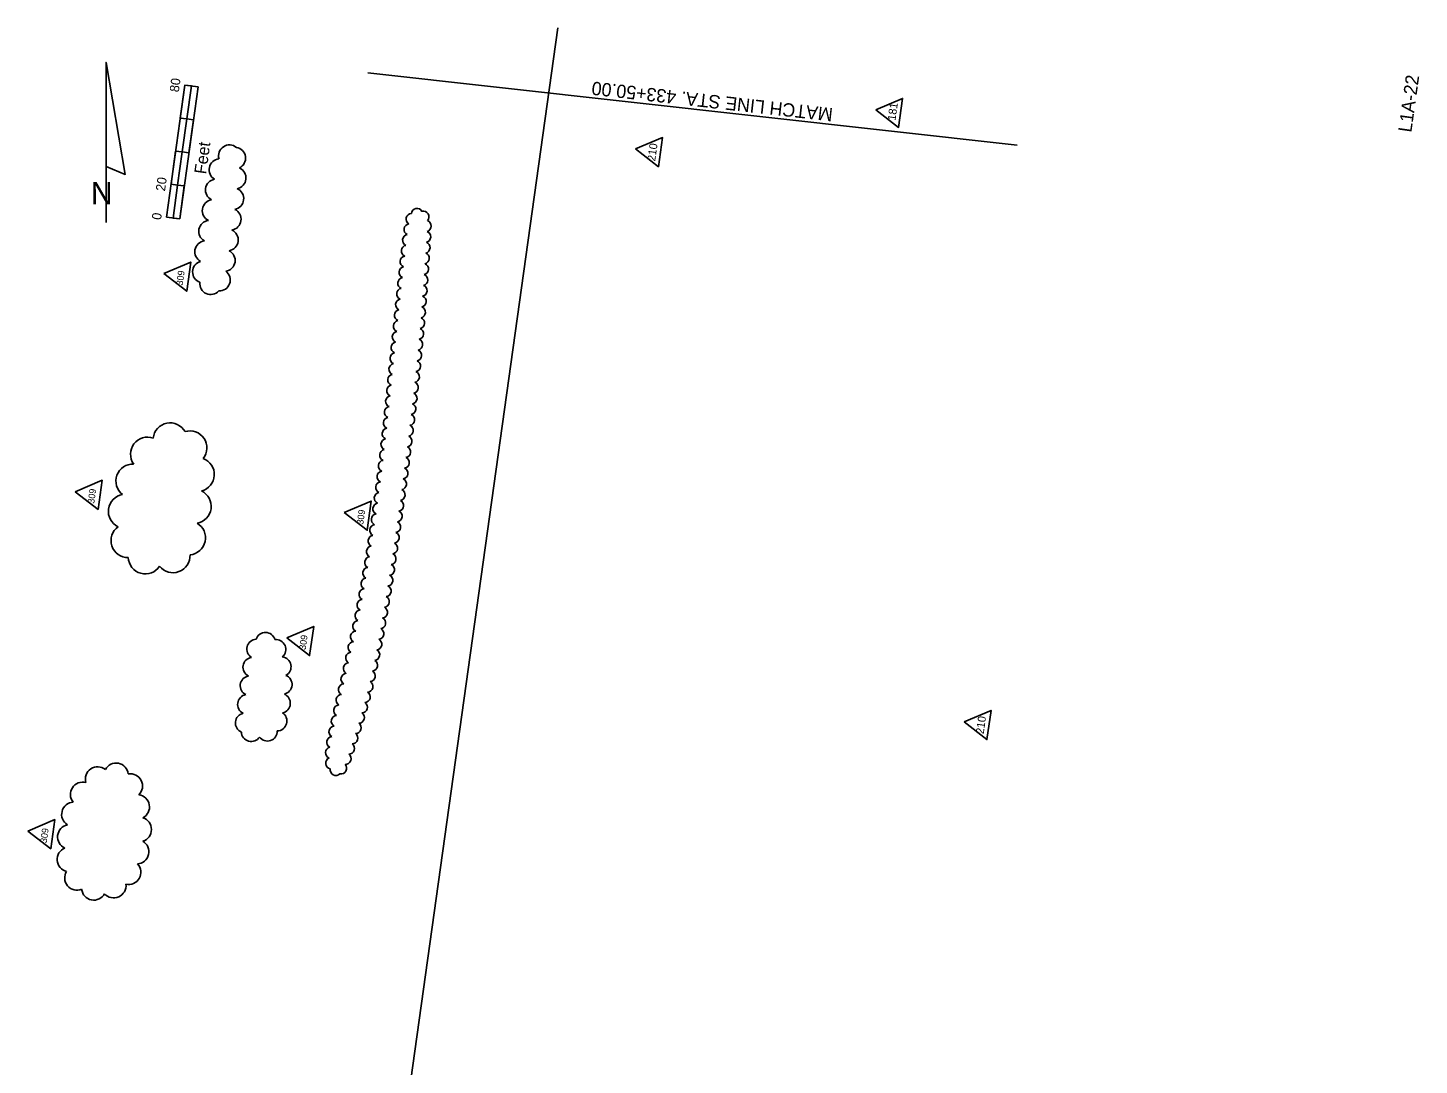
# Model space of a CAD drawing. Extents: x 930268 to 931132, y 618295 to 619577.
# Drawn here: x 930298 to 931132, y 618955 to 619577 of the extents above; entities that cross this region are included whole.
import ezdxf

# ---------------------------------------------------------------- set-up
doc = ezdxf.new("R2010")
doc.units = 0
for name, color, linetype in [('ActivePointCell_dp', 7, 'Continuous'), ('Cloud_dp', 7, 'Continuous'), ('MatchLines_dp', 7, 'Continuous'), ('NorthArw_dp', 7, 'Continuous'), ('Scale_dp', 7, 'Continuous'), ('TextShtNo', 7, 'Continuous')]:
    doc.layers.add(name, color=color, linetype=linetype)

msp = doc.modelspace()

# ---------------------------------------------------------------- linework, layer by layer
at = {"layer": 'ActivePointCell_dp'}
msp.add_line((930462.95, 618484.75), (930615.71, 619576.99), dxfattribs=at)
at = {"layer": 'Cloud_dp'}
for points in [[(930806.31, 619527.85), (930820.02, 619517.23), (930822.47, 619534.71)], [(930662.34, 619504.35), (930676.04, 619493.73), (930678.49, 619511.21)], [(930379.36, 619429.69), (930393.07, 619419.07), (930395.51, 619436.55)], [(930326.25, 619298.86), (930339.96, 619288.24), (930342.4, 619305.72)], [(930487.61, 619286.33), (930501.32, 619275.71), (930503.76, 619293.19)], [(930453.09, 619211.2), (930466.8, 619200.58), (930469.24, 619218.06)], [(930859.35, 619160.86), (930873.05, 619150.24), (930875.5, 619167.72)], [(930297.78, 619095.34), (930311.49, 619084.72), (930313.94, 619102.2)]]:
    msp.add_lwpolyline(points, close=True, dxfattribs=at)
for centre, radius, start, end in [((930418.74, 619500.23), 6.55, 51.03585, 196.03585), ((930421.82, 619498.86), 6.55, 295.85716, 80.85716), ((930413.06, 619491.9), 6.55, 95.41506, 240.41506), ((930422.08, 619486.95), 6.55, 281.58955, 66.58955), ((930410.85, 619479.72), 6.55, 98.97996, 243.97996), ((930420.71, 619474.55), 6.55, 280.79342, 65.79342), ((930408.98, 619467.36), 6.55, 98.77594, 243.77594), ((930419.13, 619462.18), 6.55, 279.66877, 64.66877), ((930528.06, 619462.32), 3.4, 94.2635, 239.2635), ((930531.18, 619465.33), 3.4, 28.62723, 173.62723), ((930534.93, 619463.65), 3.4, 317.95106, 102.95106), ((930406.83, 619454.96), 6.55, 96.59395, 241.59395), ((930417.41, 619449.81), 6.55, 279.53834, 64.53834), ((930526.82, 619456.04), 3.4, 98.56091, 243.56091), ((930536.31, 619458.17), 3.4, 285.40798, 70.40798), ((930404.47, 619442.69), 6.55, 96.60881, 241.60881), ((930525.19, 619443.22), 3.4, 101.14559, 246.14559), ((930525.94, 619449.65), 3.4, 100.60541, 245.60541), ((930535.62, 619445.25), 3.4, 283.84678, 68.84678), ((930536.01, 619451.72), 3.4, 284.24885, 69.24885), ((930415.59, 619437.47), 6.55, 278.67941, 63.67941), ((930524.48, 619436.78), 3.4, 101.31323, 246.31323), ((930535.19, 619438.79), 3.4, 283.62171, 68.62171), ((930403.15, 619430.62), 6.55, 105.91825, 250.91825), ((930412.62, 619425.77), 6.56, 267.76128, 52.76128), ((930523.79, 619430.34), 3.4, 101.40488, 246.40488), ((930534.75, 619432.32), 3.4, 283.47261, 68.47261), ((930407.5, 619423.61), 6.55, 172.86138, 317.86138), ((930523.1, 619423.89), 3.4, 101.46493, 246.46493), ((930533.81, 619419.39), 3.4, 283.28136, 68.28136), ((930534.28, 619425.86), 3.4, 283.36446, 68.36446), ((930521.75, 619411), 3.4, 101.54129, 246.54129), ((930522.42, 619417.44), 3.4, 101.50819, 246.50819), ((930533.33, 619412.93), 3.4, 283.21492, 68.21492), ((930521.08, 619404.55), 3.4, 101.56767, 246.56767), ((930532.84, 619406.46), 3.4, 283.04867, 68.04867), ((930520.41, 619398.1), 3.4, 101.58934, 246.58934), ((930531.76, 619393.55), 3.4, 282.42953, 67.42953), ((930532.32, 619400.01), 3.4, 282.72551, 67.72551), ((930519.08, 619385.2), 3.4, 101.62314, 246.62314), ((930519.74, 619391.65), 3.4, 101.60755, 246.60755), ((930531.17, 619387.1), 3.4, 282.15902, 67.15902), ((930518.42, 619378.75), 3.4, 101.63667, 246.63667), ((930530.56, 619380.65), 3.4, 281.91054, 66.91054), ((930517.75, 619372.3), 3.4, 101.64857, 246.64857), ((930529.91, 619374.21), 3.4, 281.68127, 66.68127), ((930517.09, 619365.86), 3.4, 101.65914, 246.65914), ((930528.55, 619361.32), 3.4, 281.27135, 66.27135), ((930529.24, 619367.76), 3.4, 281.46886, 66.46886), ((930515.77, 619352.96), 3.4, 101.64316, 246.64316), ((930516.43, 619359.41), 3.4, 101.66861, 246.66861), ((930527.84, 619354.88), 3.4, 281.08709, 66.08709), ((930515.1, 619346.5), 3.4, 101.48523, 246.48523), ((930527.1, 619348.44), 3.4, 280.91465, 65.91465), ((930383.16, 619329.91), 10.21, 29.0425, 174.0425), ((930514.41, 619340.05), 3.4, 101.30816, 246.30816), ((930525.58, 619335.57), 3.4, 280.60059, 65.60059), ((930526.35, 619342), 3.4, 280.75283, 65.75283), ((930369.59, 619321.35), 10.21, 70.43086, 215.43086), ((930395, 619325.08), 10.21, 321.57868, 106.57868), ((930512.97, 619327.16), 3.4, 100.93203, 245.93203), ((930513.7, 619333.61), 3.4, 101.12392, 246.12392), ((930524.8, 619329.13), 3.4, 280.45702, 65.45702), ((930512.22, 619320.72), 3.4, 100.73193, 245.73193), ((930523.99, 619322.7), 3.4, 280.32133, 65.32133), ((930360.79, 619305.23), 10.2, 87.35809, 232.35809), ((930399.41, 619309.18), 10.21, 284.44255, 69.44255), ((930511.44, 619314.28), 3.4, 100.52304, 245.52304), ((930523.18, 619316.27), 3.4, 280.19283, 65.19283), ((930509.82, 619301.41), 3.4, 100.0762, 245.0762), ((930510.64, 619307.84), 3.4, 100.30471, 245.30471), ((930521.5, 619303.42), 3.4, 279.95501, 64.95501), ((930522.35, 619309.85), 3.4, 280.0709, 65.0709), ((930356.3, 619287.09), 10.21, 99.79905, 244.79905), ((930397.57, 619290.08), 10.21, 279.53833, 64.53833), ((930508.97, 619294.97), 3.4, 99.83672, 244.83672), ((930520.64, 619297), 3.4, 279.84467, 64.84467), ((930508.09, 619288.55), 3.4, 99.58538, 244.58538), ((930519.77, 619290.57), 3.4, 279.73945, 64.73945), ((930394.16, 619271.16), 10.21, 275.04032, 60.04032), ((930507.18, 619282.12), 3.4, 99.32117, 244.32117), ((930518, 619277.73), 3.4, 279.53642, 64.53642), ((930518.89, 619284.15), 3.4, 279.63898, 64.63898), ((930357.92, 619269.57), 10.21, 125.77647, 270.77647), ((930505.27, 619269.29), 3.4, 98.74954, 243.74954), ((930506.24, 619275.7), 3.4, 99.04297, 244.04297), ((930517.1, 619271.31), 3.4, 279.38533, 64.38533), ((930504.26, 619262.88), 3.4, 98.43945, 243.43945), ((930516.17, 619264.9), 3.4, 279.21333, 64.21333), ((930368.26, 619259.74), 10.21, 182.09907, 327.09907), ((930384.87, 619260.47), 10.2, 217.94624, 2.94624), ((930503.22, 619256.47), 3.4, 98.11108, 243.11108), ((930514.26, 619252.08), 3.4, 278.82585, 63.82585), ((930515.23, 619258.49), 3.4, 279.0275, 64.0275), ((930501.03, 619243.68), 3.4, 97.39196, 242.39196), ((930502.15, 619250.07), 3.4, 97.76262, 242.76262), ((930513.27, 619245.68), 3.4, 278.60604, 63.60604), ((930499.87, 619237.29), 3.4, 96.9967, 241.9967), ((930512.26, 619239.28), 3.4, 278.36516, 63.36516), ((930498.66, 619230.91), 3.4, 96.57405, 241.57405), ((930511.21, 619232.89), 3.4, 278.09964, 63.09964), ((930496.1, 619218.19), 3.4, 95.63307, 240.63307), ((930497.4, 619224.55), 3.4, 96.12077, 241.12077), ((930509.03, 619220.12), 3.4, 277.47547, 62.47547), ((930510.14, 619226.5), 3.4, 277.80499, 62.80499), ((930440.34, 619208.53), 5.91, 16.48006, 161.48006), ((930494.73, 619211.84), 3.4, 95.10647, 240.10647), ((930507.88, 619213.74), 3.4, 277.10366, 62.10366), ((930435.03, 619204.49), 5.92, 92.83477, 237.83477), ((930446.58, 619204.31), 5.92, 310.5213, 95.5213), ((930493.31, 619205.5), 3.4, 94.65292, 239.65292), ((930506.69, 619207.38), 3.4, 276.67972, 61.67972), ((930432.75, 619193.62), 5.92, 98.47078, 243.47078), ((930449.75, 619193.93), 5.92, 298.43365, 83.43365), ((930490.42, 619192.86), 3.4, 94.61213, 239.61213), ((930491.87, 619199.18), 3.4, 94.61213, 239.61213), ((930504.14, 619194.68), 3.4, 275.61665, 60.61665), ((930505.45, 619201.02), 3.4, 276.19028, 61.19028), ((930431.08, 619182.49), 5.92, 99.53523, 244.53523), ((930450.33, 619183.25), 5.92, 282.70157, 67.70157), ((930488.98, 619186.54), 3.4, 94.61213, 239.61213), ((930502.77, 619188.36), 3.4, 274.93174, 59.93174), ((930487.53, 619180.22), 3.4, 94.61213, 239.61213), ((930501.32, 619182.05), 3.4, 274.09455, 59.09455), ((930429.52, 619171.31), 5.92, 99.53834, 244.53834), ((930449.31, 619172.03), 5.92, 281.93636, 66.93636), ((930486.09, 619173.9), 3.4, 94.61213, 239.61213), ((930498.08, 619169.55), 3.4, 271.65306, 56.65306), ((930499.76, 619175.78), 3.4, 273.0394, 58.0394), ((930428.18, 619160.17), 5.92, 101.74986, 246.74986), ((930447.27, 619161.3), 5.92, 271.49546, 56.49546), ((930483.19, 619161.26), 3.4, 94.61213, 239.61213), ((930484.64, 619167.58), 3.4, 94.61213, 239.61213), ((930496.24, 619163.35), 3.4, 270.35906, 55.35906), ((930431.76, 619154.95), 5.92, 182.16202, 327.16202), ((930441.5, 619155.25), 5.92, 216.33339, 1.33339), ((930481.75, 619154.94), 3.4, 94.61213, 239.61213), ((930494.32, 619157.17), 3.4, 270.04193, 55.04193), ((930480.45, 619148.64), 3.4, 97.08753, 242.08753), ((930490.33, 619144.85), 3.4, 269.01972, 54.01972), ((930492.35, 619151), 3.4, 269.64748, 54.64748), ((930479.71, 619142.34), 3.4, 104.56702, 249.56702), ((930479.88, 619136.04), 3.4, 113.54659, 258.54659), ((930488.22, 619138.74), 3.4, 267.75881, 52.75881), ((930339.66, 619126.5), 7.35, 51.12543, 196.12543), ((930350.75, 619128.75), 7.34, 6.79611, 151.79611), ((930359.22, 619122.36), 7.35, 314.26269, 99.26269), ((930482.55, 619132.1), 3.4, 169.56287, 314.56287), ((930485.61, 619133.01), 3.4, 258.38989, 43.38989), ((930330.65, 619117.37), 7.35, 74.57631, 219.57631), ((930363.41, 619109.81), 7.35, 297.6514, 82.6514), ((930325.41, 619105.35), 7.35, 93.34908, 238.34908), ((930322.97, 619091.88), 7.35, 101.10119, 246.10119), ((930364.6, 619096.29), 7.35, 287.35003, 72.35003), ((930363.03, 619082.96), 7.35, 274.23007, 59.23007), ((930322.71, 619078.33), 7.35, 111.73507, 256.73507), ((930327.23, 619067.23), 7.35, 147.55245, 292.55245), ((930358.19, 619070.62), 7.35, 257.90374, 42.90374), ((930349.34, 619062.64), 7.35, 221.23386, 6.23386), ((930337.35, 619061.29), 7.35, 186.59891, 331.59891)]:
    msp.add_arc(centre, radius, start, end, dxfattribs=at)
at = {"layer": 'MatchLines_dp'}
msp.add_line((930891.08, 619506.7), (930501.76, 619550.07), dxfattribs=at)
at = {"layer": 'NorthArw_dp'}
msp.add_line((930344.73, 619460.27), (930344.73, 619556.27), dxfattribs=at)
msp.add_lwpolyline([(930344.73, 619493.87), (930344.73, 619556.27), (930356.25, 619489.07)], close=True, dxfattribs=at)
at = {"layer": 'Scale_dp'}
for p, q in [((930391.96, 619542.71), (930380.93, 619463.47)), ((930388.86, 619462.37), (930399.88, 619541.6)), ((930399.88, 619541.6), (930391.96, 619542.71)), ((930380.93, 619463.47), (930388.86, 619462.37))]:
    msp.add_line(p, q, dxfattribs=at)
for points in [[(930393.16, 619522.35), (930389.2, 619522.9), (930391.96, 619542.71), (930395.92, 619542.16)], [(930394.37, 619501.99), (930390.41, 619502.54), (930393.16, 619522.35), (930397.12, 619521.8)], [(930387.65, 619482.73), (930383.69, 619483.28), (930386.44, 619503.09), (930390.41, 619502.54)], [(930388.86, 619462.37), (930384.89, 619462.92), (930387.65, 619482.73), (930391.61, 619482.18)]]:
    msp.add_lwpolyline(points, close=True, dxfattribs=at)

# ---------------------------------------------------------------- texts
at = {"layer": 'Cloud_dp'}
for s, height, p in [('181', 4.799, (930818.14, 619521.17)), ('210', 4.799, (930674.04, 619496.8)), ('309', 4, (930390.68, 619422.31)), ('309', 4, (930337.57, 619291.48)), ('309', 4, (930498.93, 619278.96)), ('309', 4, (930464.41, 619203.82)), ('210', 4.799, (930871.05, 619153.31)), ('309', 4, (930309.11, 619087.96))]:
    msp.add_text(s, height=height, rotation=82.03834, dxfattribs=at).set_placement(p)
at = {"layer": 'MatchLines_dp'}
msp.add_text('MATCH LINE STA. 433+50.00', height=8, rotation=173.6425, dxfattribs=at).set_placement((930780.96, 619528.77))
at = {"layer": 'NorthArw_dp'}
msp.add_text('N', height=13.43, dxfattribs=at).set_placement((930335.61, 619471.14))
at = {"layer": 'Scale_dp'}
for s, height, p in [('80', 5.6, (930388.3, 619538.19)), ('Feet', 7.2, (930404.67, 619488.98)), ('20', 5.6, (930380.03, 619478.78)), ('0', 5.6, (930377.64, 619461.58))]:
    msp.add_text(s, height=height, rotation=82.07942, dxfattribs=at).set_placement(p)
at = {"layer": 'TextShtNo'}
msp.add_text('L1A-22', height=8, rotation=82.03834, dxfattribs=at).set_placement((931127.57, 619513.98))

doc.saveas('drawing.dxf')
